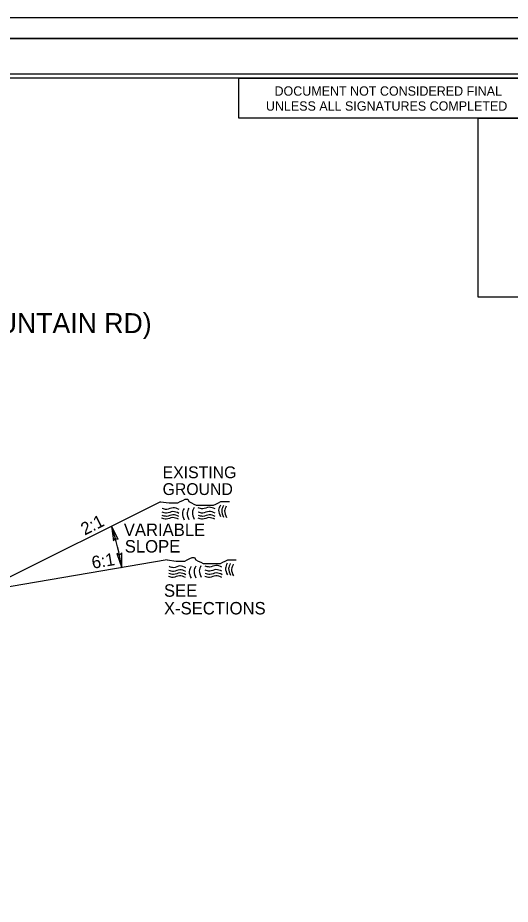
# Model space of a CAD drawing. Extents: x 2294455 to 2294795, y 719276 to 719941.
# Drawn here: x 2294677.5 to 2294739.4, y 719607.5 to 719718.8 of the extents above; entities that cross this region are included whole.
import ezdxf

# ---------------------------------------------------------------- set-up
doc = ezdxf.new("R2010")
doc.units = 0
for name, color, linetype in [('Default', 7, 'Continuous'), ('Old_Level_1', 7, 'Continuous'), ('Old_Level_11', 7, 'Continuous'), ('Old_Level_2', 7, 'Continuous'), ('Old_Level_3', 7, 'Continuous'), ('Sheet Plan CELL', 7, 'Continuous'), ('Sheet Plot Border Inside CELL', 7, 'Continuous'), ('Sheet Plot Border Outside CELL', 7, 'Continuous'), ('Sheet Sticker Exception Certification CELL', 7, 'Continuous'), ('Sheet Typical CELL', 7, 'Continuous'), ('Typical Hinge Slope Arterial CELL', 7, 'Continuous')]:
    doc.layers.add(name, color=color, linetype=linetype)

msp = doc.modelspace()

# ---------------------------------------------------------------- linework, layer by layer
at = {"layer": 'Default'}
msp.add_lwpolyline([(2294454.52, 719716.17), (2294794.52, 719716.17), (2294794.52, 719496.17), (2294454.52, 719496.17)], close=True, dxfattribs=at)
at = {"layer": 'Old_Level_11'}
for points in [[(2294690.16, 719653.28), (2294689.31, 719654.94), (2294689.55, 719653.07), (2294689.79, 719653.4)], [(2294689.97, 719651.48), (2294690.6, 719649.72), (2294690.6, 719651.6), (2294690.32, 719651.31)]]:
    msp.add_lwpolyline(points, close=True, dxfattribs=at)
at = {"layer": 'Old_Level_2'}
msp.add_line((2294454.52, 719716.17), (2294794.52, 719716.17), dxfattribs=at)
for points in [[(2294697.78, 719656.54), (2294697.02, 719656.76), (2294696.23, 719656.56), (2294695.66, 719656.68)], [(2294697.78, 719656.54), (2294697.02, 719656.76), (2294696.23, 719656.56), (2294695.66, 719656.68)], [(2294697.8, 719657.02), (2294697.04, 719657.23), (2294696.25, 719657.03), (2294695.68, 719657.15)], [(2294697.8, 719657.02), (2294697.04, 719657.23), (2294696.25, 719657.03), (2294695.68, 719657.15)], [(2294698.42, 719657.16), (2294698.21, 719656.54), (2294698.44, 719655.72)], [(2294698.42, 719657.16), (2294698.21, 719656.54), (2294698.44, 719655.72)], [(2294699.03, 719657.21), (2294698.81, 719656.59), (2294699.04, 719655.77)], [(2294699.03, 719657.21), (2294698.81, 719656.59), (2294699.04, 719655.77)], [(2294699.68, 719657.26), (2294699.47, 719656.64), (2294699.7, 719655.82)], [(2294699.68, 719657.26), (2294699.47, 719656.64), (2294699.7, 719655.82)], [(2294702.31, 719657.09), (2294701.56, 719657.3), (2294700.76, 719657.1), (2294700.19, 719657.23)], [(2294702.31, 719657.09), (2294701.56, 719657.3), (2294700.76, 719657.1), (2294700.19, 719657.23)], [(2294702.32, 719656.56), (2294701.56, 719656.78), (2294700.77, 719656.57), (2294700.2, 719656.7)], [(2294702.32, 719656.56), (2294701.56, 719656.78), (2294700.77, 719656.57), (2294700.2, 719656.7)], [(2294702.98, 719657.57), (2294702.76, 719656.95), (2294702.99, 719656.13)], [(2294702.98, 719657.57), (2294702.76, 719656.95), (2294702.99, 719656.13)], [(2294703.36, 719657.53), (2294703.16, 719656.91), (2294703.38, 719656.08)], [(2294703.36, 719657.53), (2294703.16, 719656.91), (2294703.38, 719656.08)], [(2294703.73, 719657.46), (2294703.52, 719656.84), (2294703.75, 719656.02)], [(2294703.73, 719657.46), (2294703.52, 719656.84), (2294703.75, 719656.02)], [(2294697.74, 719655.79), (2294696.98, 719656), (2294696.19, 719655.8), (2294695.61, 719655.93)], [(2294697.78, 719656.15), (2294697.03, 719656.36), (2294696.23, 719656.16), (2294695.66, 719656.29)], [(2294697.78, 719656.15), (2294697.03, 719656.36), (2294696.23, 719656.16), (2294695.66, 719656.29)], [(2294702.3, 719655.79), (2294701.55, 719656), (2294700.75, 719655.8), (2294700.18, 719655.93)], [(2294702.34, 719656.15), (2294701.59, 719656.36), (2294700.79, 719656.16), (2294700.22, 719656.29)], [(2294702.34, 719656.15), (2294701.59, 719656.36), (2294700.79, 719656.16), (2294700.22, 719656.29)], [(2294703.18, 719649.78), (2294702.43, 719650), (2294701.63, 719649.8), (2294701.06, 719649.92)], [(2294703.18, 719649.78), (2294702.43, 719650), (2294701.63, 719649.8), (2294701.06, 719649.92)], [(2294703.84, 719650.27), (2294703.63, 719649.64), (2294703.86, 719648.82)], [(2294703.84, 719650.27), (2294703.63, 719649.64), (2294703.86, 719648.82)], [(2294704.23, 719650.23), (2294704.02, 719649.6), (2294704.25, 719648.78)], [(2294704.23, 719650.23), (2294704.02, 719649.6), (2294704.25, 719648.78)], [(2294704.6, 719650.15), (2294704.39, 719649.53), (2294704.61, 719648.71)], [(2294704.6, 719650.15), (2294704.39, 719649.53), (2294704.61, 719648.71)], [(2294698.64, 719648.84), (2294697.89, 719649.06), (2294697.1, 719648.85), (2294696.52, 719648.98)], [(2294698.64, 719648.84), (2294697.89, 719649.06), (2294697.1, 719648.85), (2294696.52, 719648.98)], [(2294698.64, 719649.24), (2294697.89, 719649.46), (2294697.1, 719649.25), (2294696.53, 719649.38)], [(2294698.64, 719649.24), (2294697.89, 719649.46), (2294697.1, 719649.25), (2294696.53, 719649.38)], [(2294698.66, 719649.71), (2294697.91, 719649.93), (2294697.12, 719649.72), (2294696.55, 719649.85)], [(2294698.66, 719649.71), (2294697.91, 719649.93), (2294697.12, 719649.72), (2294696.55, 719649.85)], [(2294699.29, 719649.85), (2294699.07, 719649.23), (2294699.3, 719648.41)], [(2294699.29, 719649.85), (2294699.07, 719649.23), (2294699.3, 719648.41)], [(2294699.89, 719649.91), (2294699.68, 719649.29), (2294699.91, 719648.46)], [(2294699.89, 719649.91), (2294699.68, 719649.29), (2294699.91, 719648.46)], [(2294700.55, 719649.96), (2294700.34, 719649.34), (2294700.56, 719648.52)], [(2294700.55, 719649.96), (2294700.34, 719649.34), (2294700.56, 719648.52)], [(2294703.18, 719649.26), (2294702.43, 719649.47), (2294701.64, 719649.27), (2294701.06, 719649.4)], [(2294703.18, 719649.26), (2294702.43, 719649.47), (2294701.64, 719649.27), (2294701.06, 719649.4)], [(2294703.21, 719648.84), (2294702.46, 719649.06), (2294701.66, 719648.85), (2294701.09, 719648.98)], [(2294703.21, 719648.84), (2294702.46, 719649.06), (2294701.66, 719648.85), (2294701.09, 719648.98)], [(2294698.6, 719648.48), (2294697.85, 719648.69), (2294697.05, 719648.5), (2294696.48, 719648.62)], [(2294703.17, 719648.48), (2294702.41, 719648.69), (2294701.62, 719648.5), (2294701.04, 719648.62)]]:
    msp.add_spline(points, degree=3, dxfattribs=at)
at = {"layer": 'Sheet Plan CELL'}
msp.add_lwpolyline([(2294761.64, 719683.66), (2294735.35, 719683.66), (2294735.35, 719706.16), (2294761.64, 719706.16)], dxfattribs=at)
at = {"layer": 'Sheet Plot Border Inside CELL'}
msp.add_lwpolyline([(2294790.42, 719711.68), (2294457.12, 719711.68), (2294457.12, 719500.66), (2294790.42, 719500.66)], close=True, dxfattribs=at)
at = {"layer": 'Sheet Plot Border Outside CELL'}
for points in [[(2294793.79, 719718.76), (2294456.99, 719718.76), (2294456.99, 719498.76), (2294793.79, 719498.76)], [(2294454.52, 719496.17), (2294791.32, 719496.17), (2294791.32, 719716.17), (2294454.52, 719716.17)], [(2294794.52, 719716.17), (2294454.52, 719716.17), (2294454.52, 719496.17), (2294794.52, 719496.17)]]:
    msp.add_lwpolyline(points, close=True, dxfattribs=at)
at = {"layer": 'Sheet Sticker Exception Certification CELL'}
for p, q in [((2294705.29, 719706.16), (2294705.29, 719711.17)), ((2294705.29, 719711.17), (2294747.91, 719711.17)), ((2294747.91, 719706.16), (2294705.29, 719706.16))]:
    msp.add_line(p, q, dxfattribs=at)
at = {"layer": 'Sheet Typical CELL'}
msp.add_lwpolyline([(2294787.92, 719711.17), (2294487.92, 719711.17), (2294487.92, 719501.17), (2294787.92, 719501.17)], close=True, dxfattribs=at)
at = {"layer": 'Typical Hinge Slope Arterial CELL'}
for p in [(2294695.45, 719657.99), (2294696.31, 719650.69)]:
    msp.add_line(p, (2294672.87, 719646.71), dxfattribs=at)
for points in [[(2294695.45, 719657.99), (2294696.57, 719657.85), (2294696.88, 719657.85), (2294697.34, 719657.85), (2294697.65, 719657.85), (2294697.95, 719658.01), (2294698.26, 719658.16), (2294698.57, 719658.32), (2294698.88, 719658.32), (2294699.03, 719658.01), (2294699.34, 719657.85), (2294699.65, 719657.7), (2294699.96, 719657.55), (2294700.26, 719657.55), (2294700.57, 719657.55), (2294700.88, 719657.55), (2294701.19, 719657.55), (2294701.5, 719657.55), (2294701.8, 719657.55), (2294702.11, 719657.55), (2294702.42, 719657.7), (2294702.73, 719657.85), (2294703.04, 719658.01), (2294703.5, 719658.01), (2294703.81, 719658.01), (2294704.11, 719658.01)], [(2294696.31, 719650.69), (2294697.43, 719650.55), (2294697.74, 719650.55), (2294698.21, 719650.55), (2294698.51, 719650.55), (2294698.82, 719650.7), (2294699.13, 719650.86), (2294699.44, 719651.01), (2294699.75, 719651.01), (2294699.9, 719650.7), (2294700.21, 719650.55), (2294700.52, 719650.39), (2294700.82, 719650.24), (2294701.13, 719650.24), (2294701.44, 719650.24), (2294701.75, 719650.24), (2294702.06, 719650.24), (2294702.36, 719650.24), (2294702.67, 719650.24), (2294702.98, 719650.24), (2294703.29, 719650.39), (2294703.6, 719650.55), (2294703.9, 719650.7), (2294704.37, 719650.7), (2294704.67, 719650.7), (2294704.98, 719650.7)]]:
    msp.add_lwpolyline(points, dxfattribs=at)
msp.add_arc((2294661.98, 719645.38), 28.94, 8.6168, 19.2751, dxfattribs=at)

# ---------------------------------------------------------------- texts
at = {"layer": 'Old_Level_1'}
for s, height, rotation, p in [('EXISTING', 1.484, 360, (2294695.73, 719660.95)), ('GROUND', 1.484, 360, (2294695.73, 719658.84)), ('2:1', 1.562, 26.5651, (2294685.95, 719653.75)), ('6:1', 1.562, 9.4623, (2294686.96, 719649.58)), ('SEE', 1.562, 360, (2294695.9, 719646.07)), ('X-SECTIONS', 1.562, 360, (2294695.9, 719643.85))]:
    msp.add_text(s, height=height, rotation=rotation, dxfattribs=at).set_placement(p)
at = {"layer": 'Old_Level_3'}
msp.add_text('-Y38NE- SR 1809 (PINE MOUNTAIN RD)', height=2.5, rotation=360, dxfattribs=at).set_placement((2294632.12, 719679.17))
at = {"layer": 'Sheet Sticker Exception Certification CELL'}
for s, p in [('DOCUMENT NOT CONSIDERED FINAL', (2294709.78, 719708.97)), ('UNLESS ALL SIGNATURES COMPLETED', (2294708.7, 719707.09))]:
    msp.add_text(s, height=1.1719, dxfattribs=at).set_placement(p)
at = {"layer": 'Typical Hinge Slope Arterial CELL'}
for s, p in [('VARIABLE ', (2294690.86, 719653.7)), ('SLOPE', (2294690.98, 719651.62))]:
    msp.add_text(s, height=1.562, dxfattribs=at).set_placement(p)

doc.saveas('drawing.dxf')
